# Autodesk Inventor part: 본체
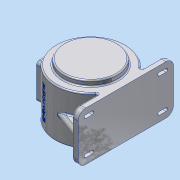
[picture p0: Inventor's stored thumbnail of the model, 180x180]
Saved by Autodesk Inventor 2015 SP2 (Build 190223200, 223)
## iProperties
Created: 2015-06
Part Number: 본체
Material: 알루미늄 6061
Document SubType Name: Modeling
Designer: AMC
Density: 2.7 g/cm^3
Appearance: 알루미늄 - 평지
Mass: 3261.98 g
Surface Area: 2301.65 cm^2
Volume: 1208.14 cm^3
Author: AMC
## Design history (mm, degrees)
sketch "스케치1"
  geometry: C1 r 85 at (0, 0); 1 further point
  constraints: 1 centre point, 1 coincident
  dimensions: "d0" = 170 diameter of C1
extrude "돌출1" new body sketch "스케치1" distance "d1" = 118; taper "d2" = 0 deg
sketch "스케치2"
  geometry: C1 r 65 at (0, 0); 1 further point
  constraints: 1 centre point, 1 coincident
  dimensions: "d3" = 130 diameter of C1
extrude "돌출2" join sketch "스케치2" distance "d4" = 13; taper "d5" = 0 deg
sketch "스케치3"
  geometry: L1 (71, -115)-(85, -115); L2 (85, -115)-(85, 115); L3 (85, 115)-(71, 115); L4 (71, 115)-(71, -115); C1 r 65 at (0, 0) reference; C2 r 85 at (0, 0) reference; C3 r 65 at (0, 0) reference; 3 further points
  constraints: 8 end point, 2 parallel, 1 coincident, 1 horizontal, 1 horizontal alignment, 1 midpoint, 1 perpendicular
  dimensions: "d6" = 230 distance of L3.end L1.start; "d7" = 14 distance of L2.end L3.end; "d8" = 85 distance from line of L2 point (0, 0)
extrude "돌출3" join sketch "스케치3" distance "d9" = 118; taper "d10" = 0 deg
node "작업 평면1"
sketch "스케치4"
  geometry: L1 (71, -115)-(71, -46.733) reference; L2 (71, 46.733)-(71, 115) reference; L3 (71, 115)-(85, 115) reference; L4 (85, 115)-(85, -115) reference; L5 (85, -115)-(71, -115) reference; L6 (71, -109)-(39.218, -97.432); A1 r 85 centre (0, 0) between (71, 46.733) and (71, -46.733) reference; 1 further point
  constraints: 2 end point, 1 point on line
  dimensions: "d11" = 6 distance from line of L5 L6.start; "d12" = 110 deg angle of L1 L6
feature "리브1" sketch "스케치4" dims "d13" = 1, "d14" = 15, "d15" = 0, "d16" = 0, "d17" = 1, "d18" = 1
node "작업 평면2"
sketch "스케치5"
  geometry: C1 r 65 at (0, 0); 1 further point
  constraints: 1 centre point, 1 coincident
  dimensions: "d19" = 130 diameter of C1
extrude "돌출4" join sketch "스케치5" distance "d20" = 3; taper "d21" = 0 deg
fillet "모깎기1" dims "d22" = 2
sketch "스케치6"
  geometry: C1 r 47.5 at (0, 0); 1 further point
  constraints: 1 centre point, 1 coincident
  dimensions: "d23" = 95 diameter of C1
extrude "돌출5" cut sketch "스케치6" distance "d24" = 11; taper "d25" = 0 deg
node "작업 평면3"
sketch "스케치7"
  geometry: L1 (-4, 118)-(14, 118) reference; L2 (14, 118)-(14, 0) reference; L3 (14, 0)-(-6, 0) reference; L4 (-6, 0)-(-6, -13) reference; L5 (-6, -13)-(-136, -13) reference; L6 (-136, -13)-(-136, 0) reference; L7 (-136, 0)-(-156, 0) reference; L8 (-156, 0)-(-156, 118) reference; L9 (-156, 118)-(-138, 118) reference; L10 (-136, 120)-(-136, 121) reference; L11 (-136, 121)-(-118.5, 121) reference; L12 (-118.5, 121)-(-118.5, 110) reference; L13 (-118.5, 110)-(-23.5, 110) reference; L14 (-23.5, 110)-(-23.5, 121) reference; L15 (-23.5, 121)-(-6, 121) reference; L16 (-6, 121)-(-6, 120) reference; L17 (-6, 121)-(-136, 121) reference; L18 (-71, -13)-(-71, 136.664); L19 (-148, 8)-(-71, 8); L20 (-71, 8)-(-71, 110); L21 (-71, 110)-(-148, 110); L22 (-148, 110)-(-148, 8); A1 r 2 centre (-4, 120) between (-6, 120) and (-4, 118) reference; A2 r 2 centre (-138, 120) between (-138, 118) and (-136, 120) reference; 1 further point
  constraints: 10 end point, 2 midpoint, 2 parallel, 1 horizontal, 1 perpendicular, 1 point on line, 1 vertical
  dimensions: "d32" = 8 distance between parallel lines of L8 L22; "d33" = 8 distance between parallel lines of L7 L19
revolve "회전1" sketch "스케치7" stored, may be unused: angle "d34" = 90 deg
sketch "스케치8"
  geometry: C1 r 31 at (0, 0); 1 further point
  constraints: 1 centre point, 1 coincident
  dimensions: "d35" = 62 diameter of C1
extrude "돌출6" join sketch "스케치8" distance "d36" = 3.5; taper "d37" = -25 deg
sketch "스케치9"
  geometry: C1 r 23.5 at (0, 0); 1 further point
  constraints: 1 centre point, 1 coincident
  dimensions: "d38" = 47 diameter of C1
extrude "돌출7" cut sketch "스케치9" distance "d39" = 14; taper "d40" = 0 deg
sketch "스케치10"
  geometry: C1 r 15 at (0, 0); 1 further point
  constraints: 1 centre point, 1 coincident
  dimensions: "d41" = 30 diameter of C1
extrude "돌출8" cut sketch "스케치10" distance "d42" = 3; taper "d43" = 0 deg
fillet "모깎기2" dims "d44" = 3
fillet "모깎기3" dims "d45" = 0.3
sketch "스케치11" dims "d46" = 110
  geometry: 3 further points
  constraints: 2 horizontal alignment, 1 coincident, 2 other
hole "구멍1" sketch "스케치11" at (55, 0) diameter "d47" = 3.242; stored, may be unused: countersink angle "d51" = 90 deg, drill point angle "d53" = 118 deg; dims "d48" = 8, "d49" = 4, "d50" = 2, "d52" = 11.8
fillet "모깎기4" dims "d57" = 18
sketch "스케치12"
  geometry: L1 (43.5, 79.201)-(43.5, 138.799) reference; L2 (43.5, 138.799)-(-58.5, 138.799) reference; L3 (-58.5, 138.799)-(-58.5, 79.201) reference; L4 (-58.5, 79.201)-(43.5, 79.201) reference; L5 (0, 0)-(-15, 0) reference; L6 (-15, 0)-(-15, 62.267) reference; L7 (-15, 62.267)-(-66.5, 62.267) reference; L8 (-66.5, 62.267)-(-66.5, 155.733) reference; L9 (-66.5, 155.733)-(-66.5, 206) reference; L10 (-48.5, 224)-(33.5, 224) reference; L11 (51.5, 206)-(51.5, 155.733) reference; L12 (51.5, 155.733)-(51.5, 62.267) reference; L13 (51.5, 62.267)-(0, 62.267) reference; L14 (0, 62.267)-(0, 0) reference; L15 (-66.5, 12)-(-66.5, 62.267) reference; L16 (33.5, -6)-(-48.5, -6) reference; L17 (51.5, 62.267)-(51.5, 12) reference; L18 (-66.5, 155.733)-(-15, 155.733) reference; L19 (-15, 155.733)-(-15, 218) reference; L20 (-15, 218)-(0, 218) reference; L21 (0, 218)-(0, 155.733) reference; L22 (0, 155.733)-(51.5, 155.733) reference; L23 (42.5, 28)-(24.5, 28); L24 (24.5, 28)-(24.5, 12); L25 (42.5, 12)-(42.5, 28); L26 (-7.5, 224)-(-7.5, -6); L27 (33.5, -6)-(-48.5, -6) reference; L28 (51.5, 109)-(-66.5, 109); L29 (-58.5, 32)-(-58.5, 186) reference; L30 (42.5, 190)-(24.5, 190); L31 (24.5, 190)-(24.5, 206); L32 (42.5, 206)-(42.5, 190); L33 (-57.5, 190)-(-39.5, 190); L34 (-39.5, 190)-(-39.5, 206); L35 (-57.5, 206)-(-57.5, 190); L36 (-57.5, 28)-(-39.5, 28); L37 (-57.5, 12)-(-57.5, 28); L38 (-39.5, 28)-(-39.5, 12); A1 r 18 centre (-48.5, 206) between (-48.5, 224) and (-66.5, 206) reference; A2 r 18 centre (33.5, 206) between (51.5, 206) and (33.5, 224) reference; A3 r 18 centre (-48.5, 12) between (-66.5, 12) and (-48.5, -6) reference; A4 r 18 centre (33.5, 12) between (33.5, -6) and (51.5, 12) reference; A5 r 9 centre (33.5, 12) between (24.5, 12) and (42.5, 12); A6 r 9 centre (33.5, 28) between (42.5, 28) and (24.5, 28); A7 r 9 centre (33.5, 206) between (42.5, 206) and (24.5, 206); A8 r 9 centre (33.5, 190) between (24.5, 190) and (42.5, 190); A9 r 9 centre (-48.5, 190) between (-57.5, 190) and (-39.5, 190); A10 r 9 centre (-48.5, 206) between (-39.5, 206) and (-57.5, 206); A11 r 9 centre (-48.5, 28) between (-39.5, 28) and (-57.5, 28); A12 r 9 centre (-48.5, 12) between (-57.5, 12) and (-39.5, 12); 4 further points
  constraints: 28 end point, 22 symmetric about line, 16 point on circle, 8 centre point, 4 coincident, 3 midpoint, 2 perpendicular, 1 horizontal, 1 parallel, 1 vertical alignment, 6 other
  dimensions: "d58" = 18 diameter of A5; "d59" = 18 diameter of A6; "d60" = 16 distance of A4.centre A6.centre; "d61" = 18 distance between parallel lines of L24 L25
extrude "돌출9" join sketch "스케치12" distance "d62" = 3; taper "d63" = 0 deg
fillet "모깎기5" dims "d64" = 3
sketch "스케치13"
  geometry: L1 (42.5, 206)-(42.5, 190) reference; L2 (24.5, 190)-(24.5, 206) reference; L3 (-57.5, 190)-(-57.5, 206) reference; L4 (-39.5, 206)-(-39.5, 190) reference; L5 (24.5, 12)-(24.5, 28) reference; L6 (42.5, 28)-(42.5, 12) reference; L7 (-39.5, 28)-(-39.5, 12) reference; L8 (-57.5, 12)-(-57.5, 28) reference; L9 (43.5, 72.875)-(43.5, 145.125) reference; L10 (43.5, 145.125)-(-58.5, 145.125) reference; L11 (-58.5, 145.125)-(-58.5, 72.875) reference; L12 (-58.5, 72.875)-(43.5, 72.875) reference; L13 (0, 1.092)-(-15, 1.092) reference; L14 (-15, 1.092)-(-15, 58) reference; L15 (-15, 58)-(-66.5, 58) reference; L16 (-66.5, 58)-(-66.5, 160) reference; L17 (-66.5, 160)-(-15, 160) reference; L18 (-15, 160)-(-15, 216.908) reference; L19 (-15, 216.908)-(0, 216.908) reference; L20 (0, 216.908)-(0, 160) reference; L21 (0, 160)-(51.5, 160) reference; L22 (51.5, 160)-(51.5, 58) reference; L23 (51.5, 58)-(0, 58) reference; L24 (0, 58)-(0, 1.092) reference; L25 (37.5, 190)-(37.5, 206); L26 (29.5, 206)-(29.5, 190); L27 (37.5, 12)-(37.5, 28); L28 (29.5, 28)-(29.5, 12); L29 (-44.5, 12)-(-44.5, 28); L30 (-52.5, 28)-(-52.5, 12); L31 (-44.5, 190)-(-44.5, 206); L32 (-52.5, 206)-(-52.5, 190); A1 r 9 centre (33.5, 206) between (42.5, 206) and (24.5, 206) reference; A2 r 9 centre (33.5, 190) between (24.5, 190) and (42.5, 190) reference; A3 r 9 centre (-48.5, 206) between (-39.5, 206) and (-57.5, 206) reference; A4 r 9 centre (-48.5, 190) between (-57.5, 190) and (-39.5, 190) reference; A5 r 9 centre (33.5, 28) between (42.5, 28) and (24.5, 28) reference; A6 r 9 centre (33.5, 12) between (24.5, 12) and (42.5, 12) reference; A7 r 9 centre (-48.5, 28) between (-39.5, 28) and (-57.5, 28) reference; A8 r 9 centre (-48.5, 12) between (-57.5, 12) and (-39.5, 12) reference; A9 r 4 centre (33.5, 206) between (37.5, 206) and (29.5, 206); A10 r 4 centre (33.5, 190) between (29.5, 190) and (37.5, 190); A11 r 4 centre (33.5, 28) between (37.5, 28) and (29.5, 28); A12 r 4 centre (33.5, 12) between (29.5, 12) and (37.5, 12); A13 r 4 centre (-48.5, 28) between (-44.5, 28) and (-52.5, 28); A14 r 4 centre (-48.5, 12) between (-52.5, 12) and (-44.5, 12); A15 r 4 centre (-48.5, 206) between (-44.5, 206) and (-52.5, 206); A16 r 4 centre (-48.5, 190) between (-52.5, 190) and (-44.5, 190); 1 further point
  constraints: 16 end point, 16 point on circle, 8 centre point, 12 other
  dimensions: "d65" = 4 radius of A10; "d66" = 4 radius of A12; "d67" = 4 radius of A14; "d68" = 4 radius of A16
extrude "돌출10" cut sketch "스케치13" stored distance "d69" = 3; taper "d70" = 0 deg
node "작업 평면4"
node "작업 평면5"
sketch "스케치14"
  geometry: L1 (-12.13, -66.5)-(-12.13, -51.5) reference; L2 (-12.13, -51.5)-(-50.267, -51.5) reference; L3 (-50.267, -51.5)-(-50.267, 0) reference; L4 (-143.733, 0)-(-50.267, 0) reference; L5 (-143.733, 0)-(-143.733, -51.5) reference; L6 (-143.733, -51.5)-(-181.87, -51.5) reference; L7 (-181.87, -51.5)-(-181.87, -66.5) reference; L8 (-181.87, -66.5)-(-143.733, -66.5) reference; L9 (-143.733, -66.5)-(-143.733, -118) reference; L10 (-50.267, -118)-(-143.733, -118) reference; L11 (-50.267, -118)-(-50.267, -66.5) reference; L12 (-50.267, -66.5)-(-12.13, -66.5) reference; L13 (-54.5, -101.5)-(-139.5, -101.5); L14 (-139.5, -101.5)-(-139.5, -16.5); L15 (-139.5, -16.5)-(-54.5, -16.5); L16 (-54.5, -16.5)-(-54.5, -101.5); 5 further points
  constraints: 8 end point, 4 midpoint, 2 parallel, 1 horizontal, 1 horizontal alignment, 1 perpendicular, 1 vertical alignment
  dimensions: "d72" = 85 distance of L14.end L15.end; "d73" = 85 distance of L13.end L14.end
extrude "돌출11" join sketch "스케치14" stored distance "d74" = 3; taper "d75" = 0 deg; dims "d14" = 15
fillet "모깎기6" dims "d76" = 7
sketch "스케치15"
  geometry: L1 (-23.5, 54.5)-(-94.5, 54.5) reference; L2 (-101.5, 61.5)-(-101.5, 132.5) reference; L3 (-94.5, 139.5)-(-23.5, 139.5) reference; L4 (-16.5, 132.5)-(-16.5, 61.5) reference; C1 r 35 at (-59, 97); A1 r 7 centre (-23.5, 61.5) between (-23.5, 54.5) and (-16.5, 61.5) reference; A2 r 7 centre (-94.5, 61.5) between (-101.5, 61.5) and (-94.5, 54.5) reference; A3 r 7 centre (-94.5, 132.5) between (-94.5, 139.5) and (-101.5, 132.5) reference; A4 r 7 centre (-23.5, 132.5) between (-16.5, 132.5) and (-23.5, 139.5) reference; 3 further points
  constraints: 2 midpoint, 1 centre point, 1 horizontal alignment, 1 vertical alignment
  dimensions: "d77" = 70 diameter of C1
extrude "돌출12" cut sketch "스케치15" stored distance "d78" = 3; taper "d79" = 0 deg; dims "d14" = 15
sketch "스케치16"
  geometry: L1 (-23.5, 54.5)-(-94.5, 54.5) reference; L2 (-101.5, 61.5)-(-101.5, 132.5) reference; L3 (-94.5, 139.5)-(-23.5, 139.5) reference; L4 (-16.5, 132.5)-(-16.5, 61.5) reference; C1 r 35 at (-59, 97) reference; A1 r 7 centre (-23.5, 61.5) between (-23.5, 54.5) and (-16.5, 61.5) reference; A2 r 7 centre (-94.5, 61.5) between (-101.5, 61.5) and (-94.5, 54.5) reference; A3 r 7 centre (-94.5, 132.5) between (-94.5, 139.5) and (-101.5, 132.5) reference; A4 r 7 centre (-23.5, 132.5) between (-16.5, 132.5) and (-23.5, 139.5) reference; 5 further points
  constraints: 4 coincident
hole "구멍2" sketch "스케치16" at (-94.5, 61.5), (-94.5, 132.5), (-23.5, 132.5), (-23.5, 61.5) diameter "d80" = 3.242; stored, may be unused: countersink angle "d84" = 90 deg, drill point angle "d86" = 118 deg; dims "d81" = 10, "d82" = 4, "d83" = 2, "d85" = 13
chamfer "모따기1" distance "d87" = 1; stored, may be unused: second distance "d88" = 2, angle "d89" = 45 deg
chamfer "모따기2" distance "d90" = 1; stored, may be unused: second distance "d91" = 2, angle "d92" = 45 deg
chamfer "모따기3" distance "d93" = 1; stored, may be unused: second distance "d94" = 2, angle "d95" = 45 deg
fillet "모깎기8" dims "d97" = 3
fillet "모깎기9" dims "d98" = 3
fillet "모깎기11" dims "d100" = 3
fillet "모깎기13" dims "d102" = 3
fillet "모깎기14" dims "d103" = 3
fillet "모깎기15" dims "d104" = 3
fillet "모깎기22" dims "d111" = 3
fillet "모깎기23" dims "d112" = 3
fillet "모깎기24" dims "d113" = 7.5
fillet "모깎기25" dims "d114" = 3
fillet "모깎기26" dims "d115" = 3
node "작업 평면8"
  node "작업 평면7"
node "작업 평면11"
  node "작업 평면10"
sketch "스케치18"
  geometry: L1 (0, 3)-(0, 115) reference; 3 further points
  constraints: 1 coincident, 1 midpoint, 1 other
feature "엠보싱2" sketch "스케치18" dims "d6" = 230, "d7" = 14, "d8" = 85, "d120" = 0.5, "d121" = 0
fillet "모깎기27" dims "d122" = 3
node "솔리드1"
mirror "대칭1"
pattern_circular "원형 패턴1" dims angle "d55" = 360 deg
node "투영된 루프1"
node "투영된 루프2"
node "작업 평면6"
node "작업 평면9"
node "절단 모서리 투영1"
node "절단 모서리 투영2"
node "절단 모서리 투영3"
node "절단 모서리 투영4"
node "절단 모서리 투영5"
node "절단 모서리 투영6"
node "절단 모서리 투영7"
node "절단 모서리 투영9"
other parameters: "d71" = -173, "d116" = 15 deg, "d119" = 205 deg
